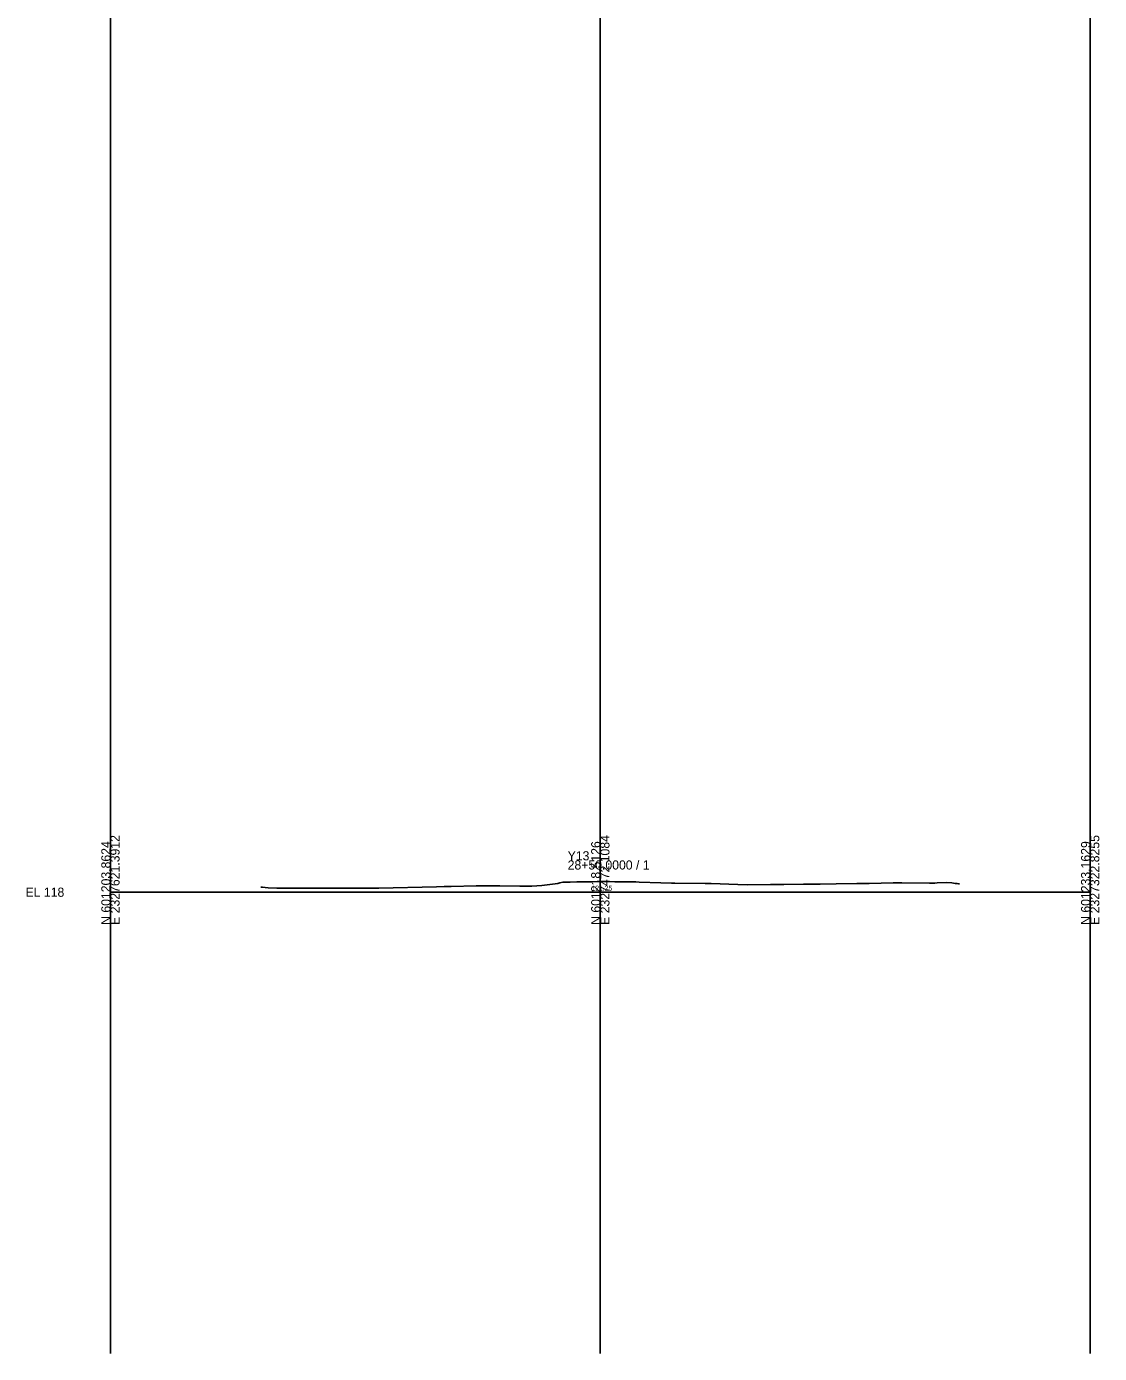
# Model space of a CAD drawing. Extents: x -26 to 1603, y -711 to 1241.
# Drawn here: x 1274.3 to 1602.8, y -141.2 to 265 of the extents above; entities that cross this region are included whole.
import ezdxf

# ---------------------------------------------------------------- set-up
doc = ezdxf.new("R2010")
doc.units = 0
for name, color, linetype in [('Exist CMT Pavement', 7, 'Continuous'), ('Exist Cross Section Cell', 7, 'Continuous'), ('Exist XS Center Line Elevation Label', 7, 'Continuous'), ('Exist XS Ground Line', 7, 'Continuous'), ('Prop XS Earthwork Shape', 7, 'Continuous'), ('Scratch_Level_9', 7, 'Continuous')]:
    doc.layers.add(name, color=color, linetype=linetype)

msp = doc.modelspace()

# ---------------------------------------------------------------- linework, layer by layer
at = {"layer": 'Exist CMT Pavement'}
for p, q in [((1449.9, 3.35), (1449.9, 3.15)), ((1449.9, 3.35), (1450, 3.35)), ((1449.9, 3.15), (1450, 3.15)), ((1450.1, 3.35), (1450, 3.35)), ((1450.1, 3.15), (1450, 3.15)), ((1450.1, 3.35), (1450.1, 3.15))]:
    msp.add_line(p, q, dxfattribs=at)
at = {"layer": 'Exist Cross Section Cell'}
for p, q in [((1450, 0), (1450, 9.74)), ((1300, 0), (1450, 0)), ((1450, 0), (1600, 0))]:
    msp.add_line(p, q, dxfattribs=at)
at = {"layer": 'Exist XS Ground Line'}
msp.add_lwpolyline([(1346.02, 1.56), (1346.59, 1.55), (1347.33, 1.46), (1348.3, 1.3), (1350.9, 1.19), (1352.86, 1.19), (1365.42, 1.21), (1379.52, 1.26), (1380.93, 1.26), (1382.16, 1.26), (1399.81, 1.69), (1402.21, 1.74), (1404.36, 1.77), (1411.96, 1.93), (1417.63, 1.96), (1419.23, 2), (1425.31, 1.88), (1429.08, 1.87), (1432.09, 2.09), (1436.99, 2.63), (1437.63, 2.88), (1438.55, 3.04), (1439.22, 3.06), (1440.75, 3.09), (1442.86, 3.14), (1443.48, 3.15), (1445.19, 3.17), (1446.21, 3.19), (1447.09, 3.2), (1449.03, 3.24), (1449.9, 3.25), (1450.79, 3.24), (1451.68, 3.24), (1452.78, 3.23), (1454.41, 3.22), (1455.29, 3.21), (1457.14, 3.19), (1458.47, 3.17), (1459.87, 3.15), (1460.47, 3.14), (1460.83, 3.13), (1461.94, 3.12), (1468.55, 2.87), (1471.81, 2.76), (1472.78, 2.77), (1482.06, 2.7), (1483.93, 2.65), (1492.11, 2.37), (1495.07, 2.3), (1502.16, 2.31), (1506.21, 2.34), (1512.21, 2.42), (1517.35, 2.48), (1522.26, 2.52), (1528.5, 2.64), (1532.31, 2.67), (1539.64, 2.88), (1542.36, 2.88), (1550.78, 2.77), (1552.41, 2.78), (1553.1, 2.82), (1556.12, 2.97), (1557.67, 2.84), (1558.61, 2.7), (1559.24, 2.65), (1559.69, 2.6), (1560.03, 2.58)], dxfattribs=at)
at = {"layer": 'Prop XS Earthwork Shape'}
msp.add_lwpolyline([(1449.9, 3.25), (1450.1, 3.25), (1450.1, 3.15), (1450, 3.15), (1449.9, 3.15)], close=True, dxfattribs=at)
at = {"layer": 'Scratch_Level_9'}
for p, q in [((1300, 1241.32), (1300, -141.18)), ((1450, 1241.32), (1450, -141.18)), ((1600, 1241.32), (1600, -141.18))]:
    msp.add_line(p, q, dxfattribs=at)

# ---------------------------------------------------------------- texts
at = {"layer": 'Exist Cross Section Cell'}
for s, p in [('E 2327621.3912', (1302.8, -10)), ('E 2327472.1084', (1452.8, -10)), ('E 2327322.8255', (1602.8, -10)), ('N 601203.8624', (1300, -10)), ('N 601218.5126', (1450, -10)), ('N 601233.1629', (1600, -10))]:
    msp.add_text(s, height=2.8, rotation=90, dxfattribs=at).set_placement(p)
for s, p in [('Y13', (1440, 9.74)), ('28+50.0000 / 1', (1440, 6.94)), ('EL 118', (1274, -1.4))]:
    msp.add_text(s, height=2.8, dxfattribs=at).set_placement(p)
at = {"layer": 'Exist XS Center Line Elevation Label'}
msp.add_text('121.25', height=1.5, dxfattribs=at).set_placement((1447.31, 0.5))

doc.saveas('drawing.dxf')
